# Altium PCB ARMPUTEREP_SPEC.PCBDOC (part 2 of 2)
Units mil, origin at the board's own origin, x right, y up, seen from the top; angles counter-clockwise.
Board outline 6000 x 4000 mil, 2 copper layers (Top Layer, Bottom Layer); 67 components, 140 nets, 541 pads, 398 vias.
Unrouted connection lines stored in the file: 6.
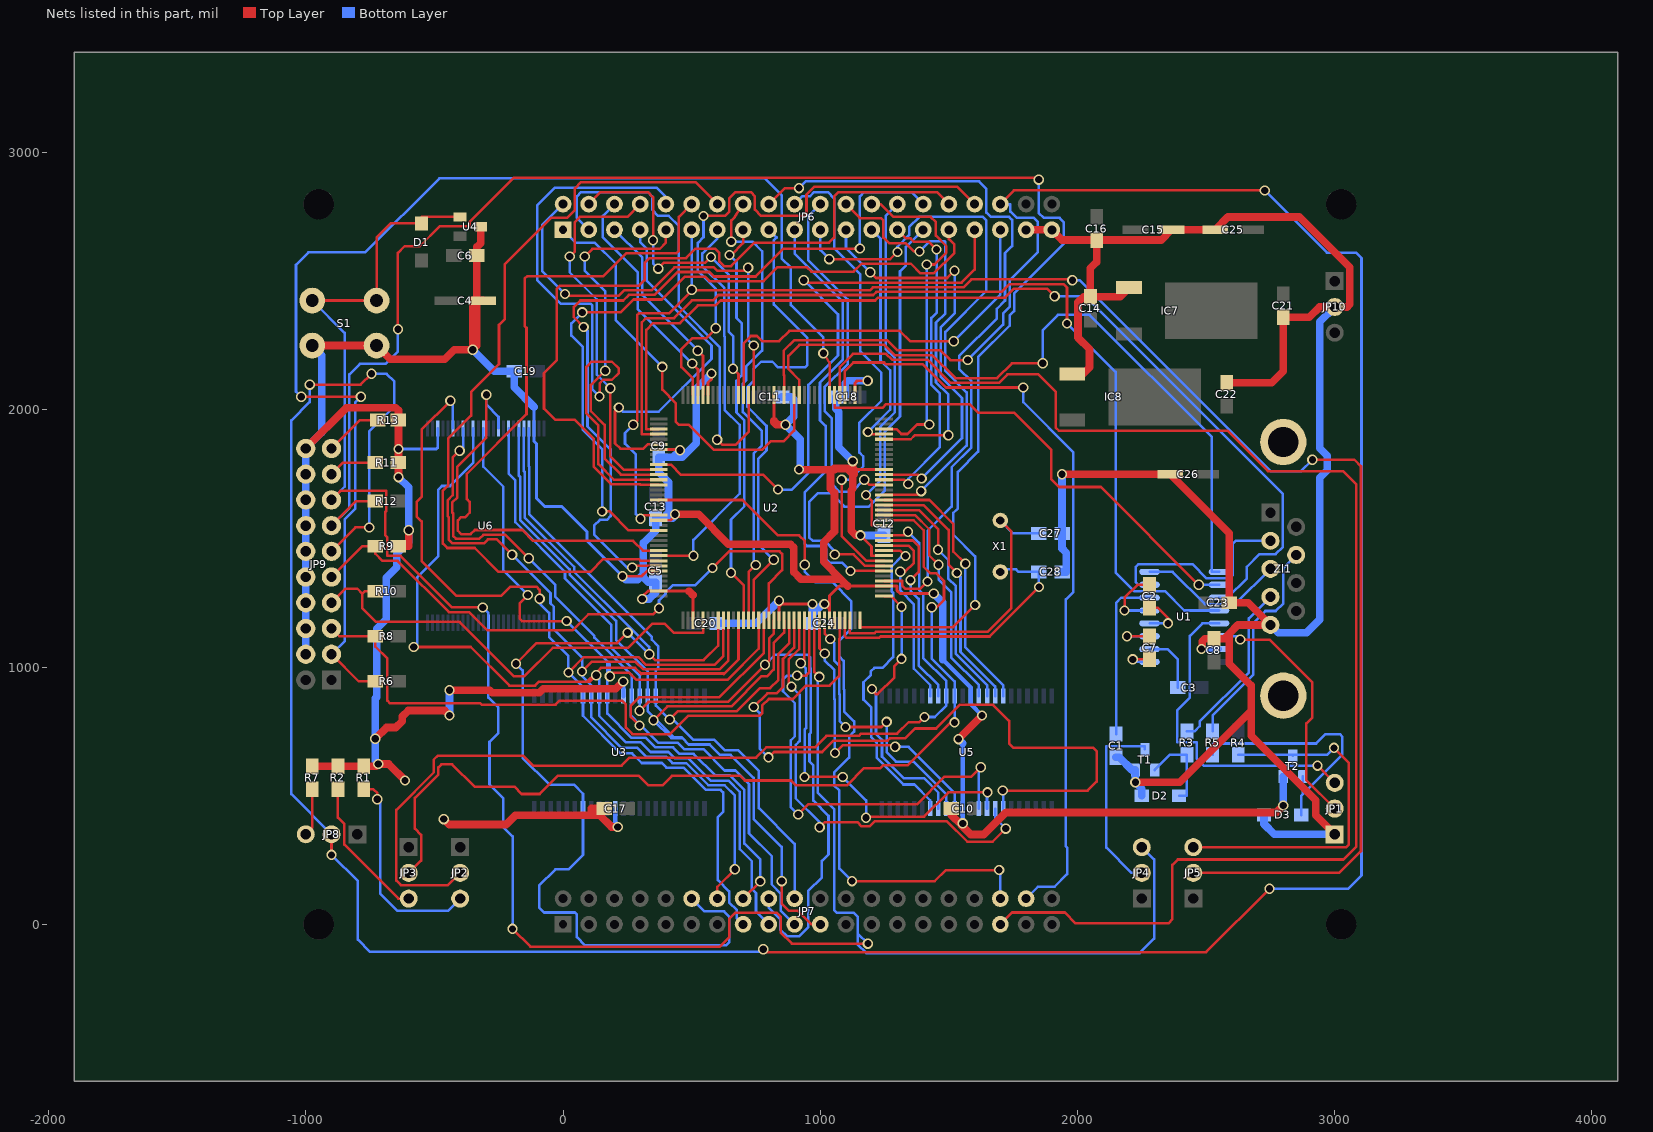
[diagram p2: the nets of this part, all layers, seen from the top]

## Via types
v1: diameter 40, hole 28, Top Layer to Bottom Layer, 398 vias

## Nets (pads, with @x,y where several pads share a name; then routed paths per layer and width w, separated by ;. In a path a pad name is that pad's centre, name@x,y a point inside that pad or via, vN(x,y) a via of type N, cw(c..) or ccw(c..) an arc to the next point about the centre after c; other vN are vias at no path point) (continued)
D7: JP7.12 U2.116 U3.16 U6.44 | length 4426.2
  Top Layer w10: v1(-183,1013) -103,1093 210,1093 v1(251,1134) ; v1(335,1050) 358,1027 546.53,1027 603.31,1083.78 U2.116@603.31,1182.01
  Bottom Layer w10: v1(-183,1013) -157,987 -157,647 -53,543 42.14,543 77.56,507.58 U3.16@77.56,450 77.56,270 21.56,214 -30,214 -93,151 -93,65 -74,46 46,46 54,38 54,-50 86,-82 634,-82 646,-70 646,30 626,50 550,50 JP7.12@500,100 ; U6.44@-152.36,1927.95 -152.36,1762 -149,1758.64 -149,1582.41 43.52,1389.89 43.52,1370 265.26,1148.26 335,1078.52 v1(335,1050) v1(251,1134)
D8: JP7.15 U2.117 U3.29 U6.30 | length 3912.3
  Top Layer w10: v1(-438,2035) -550,1923 -550,1661.5 -569.5,1642 -569.5,1585.5 -550,1566 -550,1411.97 -414.79,1276.76 -241,1276.76 -204.76,1313 -104,1313 -91,1300 v1(-91,1266) ; v1(21,979) 80.5,1038.5 292.5,1038.5 322,1009 587.99,1009 622.99,1044 U2.117@622.99,1182.01
  Bottom Layer w10: v1(-438,2035) -427.95,2024.95 U6.30@-427.95,1927.95 ; v1(-91,1266) -91,1247.57 -54,1210.57 -54,1117.67 21,1042.67 v1(21,979) 77.56,922.44 U3.29@77.56,887.01 77.56,810.77 224.01,664.31 268.69,664.31 306,627 384,627 402.01,608.99 469.01,608.99 555.3,522.7 612.3,522.7 622,513 622,437 602,417 602,172 646,128 646,85 676,55 676,24 JP7.15@700,0
D9: JP7.14 U2.118 U3.30 U6.32 | length 3382.5
  Top Layer w10: v1(-402,1841) -429,1814 -429,1668 -449,1648 -449,1587 -445,1583 -445,1496 -430,1481 -307,1481 -291.81,1496.19 -257.19,1496.19 v1(-198,1437) ; v1(74,983) 111.5,1020.5 282.5,1020.5 312,991 607.53,991 642.68,1026.15 U2.118@642.68,1182.01 ; JP7.14@600,100 600,146 v1(668,214)
  Bottom Layer w10: v1(-402,1841) -388.58,1854.42 U6.32@-388.58,1927.95 ; v1(-198,1437) -48.72,1287.72 -48.72,1247.29 -36,1234.57 -36,1146.98 74,1036.98 v1(74,983) 74,965.06 109.06,930 U3.30@109.06,887.01 109.06,805.15 228.09,686.12 288.65,686.12 322.77,652 400.32,652 425.33,626.99 479.01,626.99 565.3,540.7 628.1,540.7 668,500.8 v1(668,214)
D10: JP7.17 U2.120 U3.31 U6.34 | length 3940.4
  Top Layer w10: v1(-580,1078) -358.76,1078 -208.81,928.05 -109.12,928.05 -93.62,943.55 94,943.55 ; v1(129,968) 104.55,943.55 94,943.55 ; 304.54,973 280.54,997 147.45,997 123.72,973.28 94,943.55 ; 304.54,975 625,975 ; 625,973 682.05,1030.05 U2.120@682.05,1182.01
  Bottom Layer w10: v1(-580,1078) -566,1092 -566,1350 -485,1431 -485,1690 -471,1704 -438.98,1704 -349.21,1793.77 U6.34@-349.21,1927.95 ; v1(129,968) 140.55,956.45 U3.31@140.55,887.01 140.55,810.81 243.31,708.06 301.82,708.06 339.87,670 409.61,670 434.62,644.99 487.7,644.99 574,558.7 643.21,558.7 687,514.9 687,292.22 734,245.22 734,137 750,121 750,50 JP7.17@800,0
D11: JP7.16 U2.124 U3.32 U6.36 | length 3386.1
  Top Layer w10: v1(-137,1280) -169,1248 -169,1188 -160,1179 v1(14,1179) ; v1(182,964) 195.54,977.54 257.46,977.54 284.75,950.25 639.25,950.25 760.79,1071.79 U2.124@760.79,1182.01 ; JP7.16@700,100 v1(767,167)
  Bottom Layer w10: U6.36@-309.84,1927.95 -309.84,1778.84 -232,1701 -232,1375 v1(-137,1280) ; v1(14,1179) 172.05,1020.95 ; v1(182,964) 182,1011 172.05,1020.95 ; v1(767,167) 767,251.93 705,313.93 705,522.54 648.54,579 592,579 508.01,662.99 452.62,662.99 427.61,688 359,688 320.94,726.06 264.94,726.06 172.05,818.95 U3.32@172.05,887.01 172.05,964 172.05,1020.95
D12: JP7.19 U2.125 U3.35 U6.39 | length 3890
  Top Layer w10: v1(-298,2059) -298,1892.3 -411,1779.3 -411,1660 -431,1640 -431,1601 -427,1597 -427,1510 -416,1499 -325,1499 -309.81,1514.19 -224.19,1514.19 v1(-133,1423) ; v1(297,773) 264,806 264,850 297,883 608,883 780.47,1055.47 U2.125@780.47,1182.01
  Bottom Layer w10: v1(-298,2059) -298,2020.21 -250.79,1973 U6.39@-250.79,1927.95 ; v1(-133,1423) -30.72,1320.72 -30.72,1274.37 122,1121.64 122,1115 267,970 267,908 266.54,908 U3.35@266.54,887.01 266.54,855.85 264,853.32 264,811.61 299.81,775.81 v1@302.61,773 ; v1(297,773) v1@302.61,773 ; JP7.19@900,0 846,54 846,120.39 811.39,155 811.39,264.98 723,353.37 723,545.55 670.44,598.11 628.25,598.11 545.37,680.99 470.62,680.99 445.61,706 369.61,706 v1@302.61,773
D13: JP7.18 U2.127 U3.36 U6.41 | length 3643.1
  Top Layer w10: v1(297,830) 332,865 641,865 v1(785,1009) 801,1025 801,1111.16 819.84,1130 U2.127@819.84,1182.01
  Bottom Layer w10: U6.41@-211.42,1927.95 -211.42,1752.42 -185,1726 -185,1563 7.52,1370.48 7.52,1344.49 188,1164.02 188,1075 298.55,964.45 U3.36@298.55,887.5 298.55,831.55 v1(297,830) ; v1(785,1009) 824,1048 950,1048 960.84,1037.16 960.84,996.84 963,994.68 963,745 958,740 958,632.94 973,617.94 973,480.64 1032,421.64 1032,272.33 1006,246.33 1006,182 952.67,128.67 952.67,-11.68 918.35,-46 870,-46 845.5,-21.5 845.5,18.85 800,64.35 JP7.18@800,100
D14: JP7.21 U2.129 U3.37 U6.43 | length 3440.4
  Top Layer w10: v1(352,793) 406,847 654,847 772,965 794,965 819,990 819,1093.81 859.21,1134.02 U2.129@859.21,1182.01 ; v1(850,168) 850,81.5 879,52.5 913.5,52.5 966,0 JP7.21@1000,0
  Bottom Layer w10: U6.43@-172.05,1927.95 -172.05,1744 -167,1738.95 -167,1572.5 25.52,1379.98 25.52,1360.2 206.14,1179.58 206.14,1105.86 329.53,982.47 U3.37@329.53,887.01 329.53,866 330,866 330,827.99 358.5,799.5 430.95,727.04 460.57,727.04 463.61,724 ; v1(352,793) 421,724 463.61,724 ; v1(850,168) 850,301 741,410 741,569.11 651.11,659 610,659 570.01,698.99 488.62,698.99 463.61,724
D15: JP7.20 U2.130 U3.38 U6.45 | length 3084.1
  Top Layer w10: v1(414.75,796.25) 447.5,829 676,829 765,918 805,918 837,950 837,1050.23 878.9,1092.13 U2.130@878.9,1182.01
  Bottom Layer w10: U6.45@-132.68,1927.95 -132.68,1780 -131,1778.32 -131,1594 345.5,1117.5 345.5,1106.31 370,1081.81 370,997 361.02,988.02 U3.38@361.02,887.01 361.02,849.98 v1(414.75,796.25) 427.36,796.25 506.62,716.99 588.01,716.99 628,677 680.22,677 761,596.22 761,451.92 900,312.92 JP7.20@900,100
D16: U2.131 U5.7 | length 2697.3
  Top Layer w10: v1(741,845) 794,898 830,898 855,923 855,1032.23 898.58,1075.81 U2.131@898.58,1182.01 ; v1(799,649) 820,670 1007,670 1051,714 1262,714 1271,723 1330.26,723 1368.65,761.39 1450.39,761.39 1542,853 1672,853 1734.27,790.73 1734.27,702.73 1750,687 2060,687 2074,673 2074,555 2039,520 v1(1709,520)
  Bottom Layer w10: v1(741,845) 764.49,821.51 764.49,683.51 v1(799,649) ; v1(1709,520) 1711.02,517.98 U5.7@1711.02,450
D17: U2.132 U5.8 | length 1780.5
  Top Layer w10: v1(888,924) 877,935 877,1028.77 918.27,1070.04 U2.132@918.27,1182.01 ; v1(997.42,377) 1017.42,397 1144,397 1160,381 1192,381 1212,401 1491.54,401 1571.54,321 1670,321 v1(1721,372)
  Bottom Layer w10: v1(888,924) 919.54,892.46 919.54,712.41 904.67,697.53 904.67,489.75 997.42,397 v1(997.42,377) ; U5.8@1679.53,450 1679.53,413.47 v1(1721,372)
D18: U2.133 U5.9 | length 1547.5
  Top Layer w10: v1(924,1015) 937.95,1028.95 U2.133@937.95,1182.01 ; v1(939,573) v1(1087,573) ; v1(1178,414) 1183,419 1404,419 1498,513 v1(1650,513)
  Bottom Layer w10: v1(924,1015) 942.84,996.16 942.84,978.84 945,976.68 945,763 939,757 v1(939,573) ; v1(1087,573) 1178,482 v1(1178,414) ; U5.9@1648.03,450 1648.03,511.03 v1(1650,513)
D19: U2.134 U5.10 | length 1828.9
  Top Layer w10: v1(910,967) 944.64,967 957.64,980 U2.134@957.64,1182.01 ; v1(914,427) 953,466 1375.23,466 1483.23,574 1587,574 v1(1624,611)
  Bottom Layer w10: v1(910,967) 870,967 855,952 855,906 901.54,859.46 901.54,731.08 886,715.53 886,455 v1(914,427) ; U5.10@1616.54,450 1616.54,603.54 v1(1624,611)
D20: U2.136 U5.13 | length 1155.9
  Top Layer w10: U2.136@997.01,1182.01 997.01,1072.99 v1(1017,1053) ; v1(1057,666) 1087,696 1285,696 v1(1291,690)
  Bottom Layer w10: v1(1017,1053) 1017,1026.5 1055,988.5 1055,876 1057,874 v1(1057,666) ; v1(1291,690) 1343,690 1522.05,510.95 U5.13@1522.05,450
D21: U2.137 U5.14 | length 1090.7
  Top Layer w10: U2.137@1016.69,1182.01 1016.69,1131.31 v1(1039,1109) ; v1(1098,767) 1238,767 v1(1258,787)
  Bottom Layer w10: v1(1039,1109) 1055,1093 1055,1024.5 1073,1006.5 1073,896 1075,894 1075,790 v1(1098,767) ; v1(1258,787) 1258,669 1294.23,632.77 1363.23,632.77 1490.55,505.45 U5.14@1490.55,450
D22: U2.1 U5.15 | length 1114
  Top Layer w10: v1(1201,915) 1201,910 1216,895 1223,895 1288,960 1288,1004 v1(1316,1032) ; U2.1@1247.99,1275.51 1275,1275.51 v1(1316,1234.51)
  Bottom Layer w10: v1(1201,915) 1216.72,899.28 1216.72,740 1240,716.72 1240,652.23 1324.23,568 1402.54,568 1459.06,511.49 U5.15@1459.06,450 ; v1(1316,1032) v1(1316,1234.51)
D23: U2.10 U5.16 | length 1303.5
  Top Layer w10: U2.10@1247.99,1452.68 1310.32,1452.68 v1(1331,1432)
  Bottom Layer w10: v1(1331,1432) 1318,1432 1278,1392 1278,1293 1283,1288 1283,1038.54 1241.46,997 1210,997 1197,984 1197,970 1168,941 1168,873.23 1198.72,842.5 1198.72,726.51 1220,705.23 1220,646.77 1323.26,543.51 1365.49,543.51 1427.56,481.44 U5.16@1427.56,450
D24: U2.11 U5.29 | length 770.9
  Top Layer w10: U2.11@1247.99,1472.36 1343.82,1472.36 1364,1452.18 1364,1405 1330,1371 v1(1311,1371)
  Bottom Layer w10: v1(1311,1371) 1311,1297 1364,1244 1364,993.56 1427.56,930 U5.29@1427.56,887.01
D25: U2.12 U5.30 | length 783.8
  Top Layer w10: U2.12@1247.99,1492.05 1360.14,1492.05 1382,1470.18 1382,1369 v1(1351,1338)
  Bottom Layer w10: v1(1351,1338) 1351,1296 1382,1265 1382,1007 1459.06,929.94 U5.30@1459.06,887.01
D26: JP2.2 U2.13 U5.31 | length 3754
  Top Layer w10: JP2.2@-400,200 -448,152 -630,152 -648,170 -648,445 -502.62,590.38 -502.62,640 -486.62,656 -155,656 -116,617 228,617 259,648 750,648 790,688 978.94,688 1023.89,732.95 1151,732.95 1159.05,741 1299,741 1344,786 1385,786 v1(1405,806) ; U2.13@1247.99,1511.73 1326.73,1511.73 v1(1341,1526)
  Bottom Layer w10: v1(1341,1526) 1384,1483 1384,1300 1400,1284 1400,1036 1490.55,945.45 U5.31@1490.55,887.01 1490.55,851.55 1445,806 v1(1405,806)
D27: JP3.2 U2.16 U5.32 | length 3746.2
  Top Layer w10: JP3.2@-600,200 -552,248 -552,348 -576,372 -576,491 -484.62,582.38 -484.62,610 -472.62,622 -431,622 -343.98,534.98 -188.98,534.98 -160.72,506.72 -90.64,506.72 -19.36,578 294,578 332,540 385.79,540 422.79,577 689,577 707,559 887,559 906,540 1103,540 1170,607 1233.79,607 1245.79,619 1340.61,619 1506.66,785.05 v1(1522.05,785.05) ; U2.16@1247.99,1570.79 1363.23,1570.79 1402,1532.02 1402,1390 1427,1365 1450,1365 1481,1334 1481,1261 1453,1233 v1(1433,1233)
  Bottom Layer w10: v1(1433,1233) 1433,1033.02 1522.05,943.97 U5.32@1522.05,887.01 v1(1522.05,785.05)
D28: U2.17 U5.35 | length 927
  Top Layer w10: U2.17@1247.99,1590.47 1369,1590.47 1423.65,1535.83 1423.65,1434.35 v1(1460,1398)
  Bottom Layer w10: v1(1460,1398) 1460,1340.05 1509,1291.05 1509,1037.6 1616.54,930.06 U5.35@1616.54,887.01
D29: U2.18 U5.36 | length 968.2
  Top Layer w10: U2.18@1247.99,1610.16 1383.84,1610.16 1457.89,1536.11 v1(1457.89,1456.11)
  Bottom Layer w10: v1(1457.89,1456.11) 1496.67,1417.33 1496.67,1345 1527,1314.67 1527,1051.55 1648.55,930 U5.36@1648.55,887.5
D30: U2.19 U5.37 | length 1011.9
  Top Layer w10: U2.19@1247.99,1629.84 1402.16,1629.84 1499,1533 1499,1398 v1(1531,1366)
  Bottom Layer w10: v1(1531,1366) 1545,1352 1545,1059.01 1679.53,924.48 U5.37@1679.53,887.01
D31: U2.20 U5.38 | length 1057.7
  Top Layer w10: U2.20@1247.99,1649.53 1424.47,1649.53 1517,1557 1517,1449 v1(1564,1402)
  Bottom Layer w10: v1(1564,1402) 1564,1077.02 1711.02,930 U5.38@1711.02,887.01
GND: C1.1 C4.2 C5.2 C6.2 C8.2 C9.2 C10.2 C11.1 C12.1 C13.2 C14.2 C15.2 C16.2 C17.2 C18.2 C19.2 C20.2 C21.2 C22.2 C23.2 C24.2 C25.2 C26.2 C27.2 C28.2 D2.1 D3.1 IC7.1 IC8.1 JP1.1 JP6.37 JP6.39 JP9.4 JP9.6 JP9.8 JP9.10 JP9.12 JP9.14 JP9.16 JP9.18 JP9.20 JP10.2 R1.2 R2.2 R7.2 R9.2 R11.2 R13.2 S1.2 T1.2 T2.2 U1.15 U2.3 U2.9 U2.26 U2.38 U2.54 U2.67 U2.79 U2.93 U2.103 U2.107 U2.111 U2.128 U2.138 U2.139 U3.12 U3.34 U4.3 U5.12 U5.34 U6.27 U6.46 Zl1. Zl1.5 | length 26317.6
  Top Layer w11.22: v1(230.82,1353.18) 305.06,1353.18 325.82,1373.94 U2.103@372.01,1373.94 ; v1(308,1265) 308,1273.2 330,1295.2 U2.107@372.01,1295.2 490,1295.2 ; U2.93@372.01,1570.79 417.79,1570.79 v1@435,1588 ; U2.79@372.01,1846.38 v1@451.62,1846.38 ; U2.111@504.88,1182.01 504.88,1280.32 ; U2.67@563.94,2057.99 563.94,2106.05 577,2119.12 v1(577,2141) ; 819.84,1952 819.84,1957.16 U2.54@819.84,2057.99 ; U2.128@839.53,1182.01 839.53,1234.53 ; v1(839.53,1258) 839.53,1234.53 ; v1(970,1245) 850,1245 839.53,1234.53 ; v1(1016,1245) 1036.38,1224.62 ; U2.139@1056.06,1211 U2.139@1056.06,1182.01 U2.138@1036.38,1182.01 1036.38,1224.62 ; 1132.35,1767.64 U2.26@1247.99,1767.64 ; U2.38@1134.8,2057.99 1134.8,2103.8 1144,2113 v1(1184,2113) ; v1(1156,1512) 1199,1469 1199,1432.99 U2.9@1247.99,1432.99 ; v1(1441,1286) 1310,1286 1299,1297 1299,1314.88 U2.3@1247.99,1314.88 1107.12,1314.88 1074,1314.88 1036.38,1277.26 1036.38,1245 1036.38,1224.62
  Top Layer w30: JP9.20@-1000,1850 -842,2008 -650,2008 -640,1998 R13.2@-640,1960 v1(-640,1848) R11.2@-640,1795 v1(-640,1738.5) ; R7.2@-975,615 R2.2@-875,615 R1.2@-775,615 -726,615 v1(-718,623) -678,623 v1(-614,559) ; S1.2@-975,2250 S1.2@-725,2250 -671.71,2196.71 -460.4,2196.71 -423.1,2234 v1(-351,2234) ; v1(-729.65,721.35) -686,765 -650,765 -625,790 -625,808 -602,831 -460,831 v1(-441,812) ; R9.2@-640,1470 -600,1470 v1(-600,1531.78) ; v1(-464,409) -442.75,387.75 -221.69,387.75 -185,424.44 110.56,424.44 ; v1(-441,910) -285.07,910 -275.12,900.05 -92.7,900.05 -77.48,915.28 205.28,915.28 v1(234,944) ; U4.3@-320,2712 -320,2647.87 -335,2632.87 C6.2@-335,2600 C4.2@-335,2425 ; C4.2@-310,2425 C4.2@-335,2425 ; C17.2@160,450 110.56,450 110.56,424.44 ; v1(212.74,378.26) 188.74,378.26 142.56,424.44 110.56,424.44 ; v1(435,1594) 527,1594 643,1478 884,1478 897,1465 897,1370 925,1342 1080,1342 ; v1@451.62,1846.38 v1(455,1843) ; 490,1295.2 504.88,1280.32 ; 819.84,1952 829.84,1942 835,1942 ; 819.84,1957.16 835,1942 ; v1(865,1942) 835,1942 ; v1(917.36,1768.36) 917.36,1767.64 1050,1767.64 ; 1107.12,1314.88 1080,1342 ; v1(1126,1800.64) 1126,1750 ; 1132.35,1767.64 1132.35,1749.99 1126,1743.64 ; v1(1156,1512) 1138,1512 1120,1530 1120,1688 1126,1694 1126,1743.64 ; C10.2@1510,450 1510,424 1547.54,386.46 v1@1553.54,380.46 ; v1(1537,720) v1(1629.03,812.03) ; v1(1553.54,392.46) v1@1553.54,380.46 ; JP6.37@1800,2700 JP6.39@1900,2700 1940,2660 C16.2@2075,2660 ; v1(1940,1750) C26.2@2360,1750 2590,1520 C23.2@2590,1250 2664,1250 Zl1.5@2750,1164 2624,1164 2590,1130 ; IC8.1@1980,2140 2021.58,2140 2047,2165.42 2047,2236 2002,2281 2002,2418 2024,2440 C14.2@2050,2440 ; IC7.1@2200,2475 2165,2440 C14.2@2050,2440 ; v1(2225,552) 2397,552 2675,830 ; v1(2482,1070) 2485,1073 2485,1100 2495,1110 C8.2@2530,1110 2570,1110 2590,1130 ; C22.2@2580,2105 2755,2105 2800,2150 C21.2@2800,2360 2901,2360 2941,2400 JP10.2@3000,2400 3048,2400 3058,2410 3058,2554 2862,2750 2585,2750 C25.2@2535,2700 C15.2@2365,2700 2325,2660 C16.2@2075,2660 ; v1(2800,462) 2773,435 1722,435 1636,349 1585,349 v1@1553.54,380.46 ; JP1.1@3000,350 2926,424 2926,482 2675,733 2675,830 ; v1(-351,2234) -335,2250 C4.2@-335,2425 ; v1(-351,2234) -351,2425 C4.2@-335,2425 ; 1050,1767.64 1056.78,1767.64 1060.88,1771.74 ; 1050,1767.64 1040,1757.64 1040,1693 1055,1678 1055,1527 1013,1485 1013,1409 1080,1342 ; 1050,1767.64 1054.11,1771.74 1060.88,1771.74 ; 1060.88,1771.74 1104.26,1771.74 1126,1750 ; 1126,1743.64 1126,1750 ; C14.2@2050,2440 2050,2550 2075,2575 C16.2@2075,2660 ; 2590,1130 2590,1013 2675,928 2675,830
  Bottom Layer w11.22: v1(-640,1848) -492.01,1848 -487.01,1853 U6.27@-487.01,1927.95 ; -112.99,2010.99 U6.46@-112.99,1927.95 -112.99,1878 -103,1868.01 -103,1656 -71,1624 -5,1624 93,1526 93,1491 v1(230.82,1353.18) 245,1339
  Bottom Layer w16.83: v1@203.54,387.46 U3.12@203.54,450 ; v1(234,944) 235.04,942.96 U3.34@235.04,887.01 ; 1476,1029.62 1585.04,920.58 U5.34@1585.04,887.01 1585.04,856.02 v1(1629.03,812.03) ; v1(1553.54,392.46) U5.12@1553.54,450 1553.54,703.46
  Bottom Layer w22.8: v1(2482,1070) U1.15@2550,1070
  Bottom Layer w30: JP9.4@-1000,1050 JP9.6@-1000,1150 JP9.8@-1000,1250 JP9.10@-1000,1350 JP9.12@-1000,1450 JP9.14@-1000,1550 JP9.16@-1000,1650 JP9.18@-1000,1750 JP9.20@-1000,1850 -937.71,1912.29 -937.71,2212.71 S1.2@-975,2250 ; v1(-718,623) -729.65,634.65 v1(-729.65,721.35) -729.65,878.28 -724,883.93 -724,1149 -687,1186 -687,1347 -646,1388 -646,1440 -600,1486 v1(-600,1531.78) -600,1698.5 v1(-640,1738.5) ; v1(-441,812) v1(-441,910) ; v1(-351,2234) -267,2150 C19.2@-190,2150 -190,2088 -112.99,2010.99 ; v1@203.54,387.46 v1(212.74,378.26) ; 245,1339 290,1339 312,1361 ; v1(308,1265) 335,1265 360,1290 C5.2@360,1330 332,1330 312,1350 312,1361 ; v1@435,1588 426.21,1579.21 420.21,1579.21 ; v1(435,1594) 432,1591 420.21,1579.21 ; v1(455,1843) 427.43,1815.43 ; v1(577,2141) 518,2082 518,1870 473,1825 463.43,1815.43 455,1815.43 427.43,1815.43 ; C20.2@600,1170 751.53,1170 v1(839.53,1258) ; C11.1@850,2050 887,2050 897,2040 897,1974 v1(865,1942) 922,1885 922,1773 v1(917.36,1768.36) ; C24.2@970,1170 970,1205 ; v1(970,1245) 970,1205 ; v1(1016,1245) 1010,1245 990,1225 970,1205 ; v1(1126,1800.64) 1072,1854.64 1072,1992 1060,2004 C18.2@1060,2050 1097,2050 1097,2103.12 1106.88,2113 v1(1184,2113) ; v1(1156,1512) 1156.27,1511.73 C12.1@1247.99,1511.73 ; v1(1441,1286) 1476,1251 1476,1029.62 ; v1(1537,720) 1553.54,703.46 ; C28.2@1940,1370 1956,1370 1956,1445 1940,1461 C27.2@1940,1520 v1(1940,1750) ; C1.1@2150,650 2162,650 2212,600 T1.2@2225,600 v1(2225,552) 2250,527 D2.1@2250,500 ; D3.1@2725,425 2725,390 2765,350 JP1.1@3000,350 ; Zl1.5@2750,1164 2781,1133 2890,1133 2942,1185 2942,1736 2971,1765 2971,1822 2942,1851 2942,2342 JP10.2@3000,2400 ; v1(2800,462) T2.2@2800,575 ; 312,1361 312,1482 360,1530 C13.2@360,1579.21 390,1579.21 ; 390,1579.21 420.21,1579.21 ; 390,1579.21 410,1599.21 410,1719.01 372.01,1757 C9.2@372.01,1815.43 427.43,1815.43
NetC1_2: C1.2 U1.6 | length 648.3
  Bottom Layer w10: C1.2@2150,740 2150,1250 2170,1270 U1.6@2280,1270
NetC2_1: C2.1 U1.5 | length 264.7
  Top Layer w10: v1(2183,1220) 2183,1270 2233,1320 C2.1@2280,1320
  Bottom Layer w10: v1(2183,1220) U1.5@2280,1220
NetC2_2: C2.2 U1.4 | length 180.6
  Top Layer w10: C2.2@2280,1230 2312,1230 2352,1190 v1(2352,1170)
  Bottom Layer w10: U1.4@2280,1170 v1(2352,1170)
NetC3_2: C3.2 U1.2 | length 236.6
  Bottom Layer w10: U1.2@2280,1070 2350,1070 2390,1030 C3.2@2390,920
NetC7_1: C7.1 U1.3 | length 176
  Top Layer w10: v1(2192,1120) C7.1@2280,1120
  Bottom Layer w10: v1(2192,1120) U1.3@2280,1120
NetC7_2: C7.2 U1.1 | length 134.1
  Top Layer w10: v1(2215,1030) C7.2@2280,1030
  Bottom Layer w10: v1(2215,1030) 2225,1020 U1.1@2280,1020
NetC27_1: C27.1 U2.142 X1.2 | length 1247.3
  Top Layer w10: U2.142@1115.12,1182.01 1115.12,1132 1211,1132 1216,1137 1650.54,1137 1743,1229.46 1743,1527 X1.2@1700,1570
  Bottom Layer w10: X1.2@1700,1570 1750,1520 C27.1@1850,1520
NetC28_1: C28.1 U2.141 X1.1 | length 1117.6
  Top Layer w10: U2.141@1095.43,1182.01 1095.43,1120 1101.43,1114 1229,1114 1234,1119 1658,1119 v1(1850,1311)
  Bottom Layer w10: X1.1@1700,1370 1709.54,1379.54 1761,1379.54 1770.54,1370 C28.1@1850,1370 v1(1850,1311)
NetD2_2: D2.2 R3.2 T1.1 | length 339.9
  Bottom Layer w10: T1.1@2300,600 2360,660 R3.2@2425,660 2425,500 D2.2@2395,500
NetD3_2: D3.2 R5.2 T2.1 | length 1007.3
  Bottom Layer w10: R5.2@2525,660 2525,703 2928,703 2964,739 3020,739 3030,729 3030,660 2875,505 ; D3.2@2870,425 2870,500 2875,505 ; T2.1@2875,575 2875,505
NetJP1_2: JP1.2 U1.14 | length 982.6
  Top Layer w10: v1(2633,1107) 2746,1107 2913,940 2913,804 2890,781 2890,560 JP1.2@3000,450
  Bottom Layer w10: U1.14@2550,1120 2620,1120 v1(2633,1107)
NetJP1_3: JP1.3 U1.13 | length 1282.9
  Top Layer w10: v1(2933,617) JP1.3@3000,550
  Bottom Layer w10: U1.13@2550,1170 2486,1170 2437,1121 2437,882 2387,832 2387,707 2463,707 2463,644 2490,617 v1(2933,617)
NetJP2_3: JP2.3 R1.1 | length 812.8
  Top Layer w10: R1.1@-775,525 -737,525 -722,510 v1(-722,486)
  Bottom Layer w10: v1(-722,486) -711,475 -711,120 -643,52 -448,52 JP2.3@-400,100
NetJP3_3: JP3.3 R2.1 | length 562.3
  Top Layer w10: R2.1@-875,525 -875,415 -850,390 -850,310 -640,100 JP3.3@-600,100
NetJP4_2: JP4.2 T1.3 | length 736.6
  Bottom Layer w10: JP4.2@2250,200 2210,200 2112,298 2112,693 2262,693 T1.3@2262,680
NetJP5_3: JP5.3 R4.2 T2.3 | length 1396.9
  Top Layer w10: JP5.3@2450,300 3045,300 3055,310 3055,628 v1(2997,686)
  Bottom Layer w10: R4.2@2625,660 T2.3@2837,660 ; T2.3@2837,655 T2.3@2837,660 ; v1(2997,686) 2971,660 T2.3@2837,660
NetJP8_3: JP8.3 R7.1 | length 185.4
  Top Layer w10: JP8.3@-1000,350 -975,375 R7.1@-975,525
NetJP9_17: JP9.17 R11.1 | length 188.6
  Top Layer w10: JP9.17@-900,1750 -855,1795 R11.1@-730,1795
NetJP9_19: JP9.19 R13.1 | length 225.6
  Top Layer w10: JP9.19@-900,1850 -790,1960 R13.1@-720,1960
NetR3_1: R3.1 Zl1.4 | length 675.2
  Bottom Layer w10: R3.1@2425,750 2455,750 2475,770 2475,788 2666,979 2666,1189 Zl1.4@2750,1273
NetR5_1: R5.1 Zl1.7 | length 844.1
  Bottom Layer w10: R5.1@2525,750 2525,812 2684,971 2684,1172 2730,1218 2770,1218 2800,1248 2800,1386 Zl1.7@2850,1436
NetU1_7: U1.7 Zl1.2 | length 799
  Bottom Layer w10: U1.7@2280,1320 2236,1320 2227,1329 2227,1390 2237,1400 2446.46,1400 2501.46,1345 2590,1345 2603,1358 2603,1479 2615,1491 Zl1.2@2750,1491
NetU1_8: U1.8 Zl1.3 | length 578.5
  Bottom Layer w10: U1.8@2280,1370 2370,1370 2495,1245 2613,1245 Zl1.3@2750,1382
P0.0: U1.10 U2.42 | length 1906.2
  Top Layer w10: U2.42@1056.06,2057.99 1056.06,2009 1243,2009 1256,2022 1581,2022 1613.88,1989.12 1753.38,1989.12 1898,1844.5 1898,1730 1928,1700 2091,1700 v1(2471,1320)
  Bottom Layer w10: v1(2471,1320) U1.10@2550,1320
P0.1: U1.9 U2.49 | length 2813.4
  Top Layer w10: U2.49@918.27,2057.99 918.27,2116.73 876,2159 876,2210 919,2253 1249,2253 1289,2213 1435,2213 1525,2123 1687.24,2123 1745.24,2181 v1(1865,2181)
  Bottom Layer w10: v1(1865,2181) 1865,2310 1924,2369 2047,2369 2522,1894 2522,1370 U1.9@2550,1370
P0.2: JP6.1 U2.50 | length 1644.7
  Top Layer w10: v1(386,2167) 386,2078.46 438,2026.46 438,1954 450,1942 488.98,1942 585.34,1845.64 774.64,1845.64 806.73,1877.73 856.73,1877.73 898.58,1919.58 U2.50@898.58,2057.99
  Bottom Layer w10: JP6.1@0,2700 51,2649 124,2649 205,2568 205,2348 v1(386,2167)
P0.3: JP6.2 U2.58 | length 1698.1
  Top Layer w10: v1(8,2450) 8,2443 216,2443 237.86,2464.86 343.86,2464.86 433,2554 586.5,2554 600,2540.5 707.5,2540.5 v1(719.5,2552.5) ; v1(741,2250.5) 741,2087.1 741.1,2087 U2.58@741.1,2057.99
  Bottom Layer w10: JP6.2@0,2800 -80,2720 -80,2538 v1(8,2450) ; v1(719.5,2552.5) 719.5,2272 v1(741,2250.5)
P0.4: JP6.3 U2.59 | length 1833.7
  Top Layer w10: v1(599,1884) 619.36,1863.64 670.64,1863.64 721.42,1914.42 U2.59@721.42,2057.99
  Bottom Layer w10: JP6.3@100,2700 54,2746 54,2830 70,2846 330,2846 346,2830 346,2778 370,2754 411,2754 450,2715 450,2402.71 610,2242.71 610,1895 v1(599,1884)
P0.5: JP6.4 U2.61 | length 1366.6
  Top Layer w10: JP6.4@100,2800 146,2846 330,2846 350,2826 v1(350,2659) ; v1(370,2549) 393,2572 553,2572 v1(575,2594) ; v1(661,2160.05) 682.05,2139 U2.61@682.05,2057.99
  Bottom Layer w10: v1(350,2659) 350,2569 v1(370,2549) ; v1(575,2594) 645,2524 645,2302.85 661,2286.85 v1(661,2160.05)
P0.6: JP6.5 U2.68 | length 784.6
  Top Layer w10: v1(524,2230) 544,2210 544,2108.25 544.25,2108 U2.68@544.25,2057.99
  Bottom Layer w10: JP6.5@200,2700 308,2592 308,2446 v1(524,2230)
P0.7: JP6.6 U2.69 | length 914.1
  Top Layer w10: v1(502,2180) 524.57,2157.43 U2.69@524.57,2057.99
  Bottom Layer w10: JP6.6@200,2800 154.5,2754.5 154.5,2670.5 290,2535 290,2392 v1(502,2180)
P0.8: U1.11 U2.75 | length 3866.2
  Top Layer w10: U2.75@372.01,1925.12 324,1925.12 324,2311 350,2337 455,2337 524,2406 593.15,2406 612.15,2425 1213.59,2425 1224.59,2436 1719,2436 1754,2471 1882,2471 v1(1911,2442)
  Bottom Layer w10: v1(1911,2442) 2028.27,2442 2798,1672.27 2798,1467 2770,1439 2707,1439 2658,1390 2658,1345 2583,1270 U1.11@2550,1270
P0.9: U1.12 U2.76 | length 3870.3
  Top Layer w10: U2.76@372.01,1905.43 306,1905.43 306,2340 322.86,2356.86 431.64,2356.86 500.77,2426 583.5,2426 603.9,2446.4 1205.94,2446.4 1217.89,2458.36 1705.36,2458.36 1736,2489 1945,2489 1959,2475 v1(1959,2336)
  Bottom Layer w10: v1(1959,2336) 2147.96,2147.04 2147.96,1367.04 2220,1295 2340,1295 2415,1220 U1.12@2550,1220
P0.10: JP6.7 U2.78 | length 1399.5
  Top Layer w10: v1(217,2009) 202,1994 202,1870 223,1849 312,1849 329.06,1866.06 U2.78@372.01,1866.06
  Bottom Layer w10: v1(217,2009) 233,1993 372,1993 577.25,2198.25 577.25,2250 326,2501.25 326,2626 300,2652 JP6.7@300,2700
P0.11: JP6.8 U2.83 | length 1477
  Top Layer w10: v1(26,2596) 46,2616 46,2730 66,2750 250,2750 JP6.8@300,2800 ; v1(184,2084) 184,1819.01 235.38,1767.64 U2.83@372.01,1767.64
  Bottom Layer w10: v1(26,2596) 26,2534.98 131,2429.98 131,2137 v1(184,2084)
P0.12: JP6.9 U2.84 | length 1488.2
  Top Layer w10: v1(84,2596) 114,2626 376,2626 400,2650 JP6.9@400,2700 ; v1(164,2152) 108.49,2096.49 108.49,1994.51 162,1941 162,1810.36 224.41,1747.95 U2.84@372.01,1747.95
  Bottom Layer w10: v1(84,2596) 84,2541.5 164,2461.5 v1(164,2152)
P0.13: JP6.10 U2.85 | length 2446.2
  Top Layer w10: v1(142,2052) 142,2103 156,2117 190,2117 217,2144 217,2160 190,2187 110,2187 90.49,2167.49 90.49,1986.51 137,1940 137,1789 197.73,1728.27 U2.85@372.01,1728.27
  Bottom Layer w10: v1(142,2052) 113,2081 113,2407 108,2412 -8,2412 -101,2505 -101,2794 -31,2864 364,2864 400,2828 JP6.10@400,2800
P0.14: JP5.2 JP6.11 U2.92 | length 6540.2
  Top Layer w10: v1(273,1942) 288,1957 288,2368.42 294.44,2374.86 411.77,2374.86 501.41,2464.5 v1@502.5,2464.5 ; v1(301,1577) 314.47,1590.47 U2.92@372.01,1590.47 ; v1(500,2467) v1@502.5,2464.5 ; v1(1980,2504) 1977,2507 1587,2507 1556.5,2476.5 1204.87,2476.5 1192.87,2464.5 v1@502.5,2464.5 ; JP5.2@2450,200 3017.2,200 3102,284.8 3102,1780 3076,1806 v1(2913,1806)
  Bottom Layer w10: v1(273,1942) 241,1910 241,1868.6 283,1826.6 283,1595 v1(301,1577) ; v1(500,2467) JP6.11@500,2700 ; v1(1980,2504) 2008.4,2504 2750.4,1762 2869,1762 v1(2913,1806)
P0.15: JP6.12 U2.99 | length 2784.4
  Top Layer w10: U2.99@372.01,1452.68 310.32,1452.68 272,1491 -116,1491 -158,1533 -343,1533 -359,1517 -396,1517 -409,1530 -409,1570 -396,1583 -380,1583 -363,1600 -363,1642 -373.6,1652.6 -373.6,1751.58 -142,1983.18 -142,2319 -149,2326 -149,2510 -139,2520 157,2520 245,2608 440,2608 450,2618 450,2750 JP6.12@500,2800
P0.16: JP6.13 U2.100 | length 1560.6
  Top Layer w10: U2.100@372.01,1432.99 v1(507,1432.99)
  Bottom Layer w10: v1(507,1432.99) 507,1494 687,1674 687,1941 628,2000 628,2285 627,2286 627,2473 542,2558 542,2608 600,2666 JP6.13@600,2700
P0.17: JP6.14 U2.101 | length 3136.4
  Top Layer w10: U2.101@372.01,1413.31 301.69,1413.31 295,1420 156,1420 106,1370 -250.24,1370 -343.24,1463 -450,1463 -467,1480 -467,1686 -447,1706 -447,1888 -357,1978 -357,2070 -248.98,2178.02 -248.98,2330.02 -227,2352 -227,2565 -46,2746 15,2746 46,2777 46,2861 70,2885 515,2885 JP6.14@600,2800
P0.18: JP6.15 U2.121 | length 1626.2
  Top Layer w10: v1(647,2602) 654,2602 700,2648 JP6.15@700,2700 ; v1(653,1367) 701.73,1318.27 U2.121@701.73,1182.01
  Bottom Layer w10: v1(647,2602) 674.22,2574.78 674.22,2356.99 694,2337.21 694,2132.9 674.22,2113.11 674.22,1989.78 705,1959 705,1625.27 653,1573.27 v1(653,1367)
P0.19: JP6.16 U2.122 | length 1821
  Top Layer w10: v1(654,2654) 654,2736.5 667.68,2750.18 JP6.16@700,2800 ; U2.122@721.42,1182.01 721.42,1369.42 v1(749,1397)
  Bottom Layer w10: v1(654,2654) 736.5,2654 774,2616.5 774,2230 712,2168 712,2114.9 699,2101.9 699,1991.73 773,1917.73 773,1862 741,1830 741,1405 v1(749,1397)
P0.20: JP6.17 U2.123 | length 1917.1
  Top Layer w10: U2.123@741.1,1182.01 741.1,1339.1 v1(819,1417)
  Bottom Layer w10: JP6.17@800,2700 830,2670 819.5,2659.5 819.5,2409.5 950,2279 950,2175 940,2165 836,2165 814,2187 770,2187 741,2158 741,2112.87 717,2088.87 717,2012 791,1938 791,1842 759,1810 759,1477 v1(819,1417)
P0.21: JP6.18 U2.4 | length 2882.2
  Top Layer w10: JP6.18@800,2800 862,2862 v1(917,2862) ; U2.4@1247.99,1334.57 1318,1334.57 1318,1317 1330,1305 1389,1305 v1(1417,1333)
  Bottom Layer w10: v1(917,2862) 943,2888 1617,2888 1646,2859 1646,2767 1663,2750 1734.54,2750 1746,2738.54 1746,2637 1718,2609 1718,2424.36 1686.64,2393 1686.64,2355.72 1540,2209.07 1540,2159 1587,2112 1587,1853.35 1510.5,1776.85 1510.5,1623.5 1417,1530 v1(1417,1333)
P0.23: JP6.19 U2.6 | length 1752.4
  Top Layer w10: v1(1117.13,1373.94) U2.6@1247.99,1373.94
  Bottom Layer w10: JP6.19@900,2700 900,2608 1088,2420 1088,2195 999,2106 999,1959.19 1020.95,1937.24 1020.95,1759.76 939,1677.81 939,1480 948.16,1470.84 1009.16,1470.84 1023,1457 1023,1420 1038.02,1404.98 1086.09,1404.98 v1(1117.13,1373.94)
P0.24: JP6.20 U2.8 | length 1870.6
  Top Layer w10: v1(1083,1728) 1083,1510.31 1180,1413.31 U2.8@1247.99,1413.31
  Bottom Layer w10: JP6.20@900,2800 931,2831 961,2831 976,2846 1030,2846 1054,2822 1054,2629 1156,2527 1156,2226 1237,2145 1237,2035 1152,1950 1152,1834 1167,1819 1167,1780 1115,1728 v1(1083,1728)
P0.25: JP6.21 U2.21 | length 2218.9
  Top Layer w10: v1(1035,2586) 1272,2586 v1(1300,2614) ; U2.21@1247.99,1669.21 1377.21,1669.21 v1(1392,1684)
  Bottom Layer w10: JP6.21@1000,2700 1000,2621 v1(1035,2586) ; v1(1300,2614) 1300,2634 1345.5,2679.5 1345.5,2710 1385.5,2750 1632,2750 1646,2736 1646,2463 1486,2303 1486,2151.28 1569,2068.28 1569,1861 v1(1392,1684)
P0.27: JP6.22 U2.23 | length 1462
  Top Layer w10: v1(1170.58,1728.58) 1190.58,1708.58 U2.23@1247.99,1708.58
  Bottom Layer w10: JP6.22@1000,2800 954,2754 954,2581.43 1106,2429.43 1106,2177 1017,2088 1017,1994.68 1044,1967.68 1044,1712.98 1075.63,1681.35 1123.35,1681.35 v1(1170.58,1728.58)
P0.28: JP6.23 U2.25 | length 1635
  Top Layer w10: v1(1194,2535) 1216.5,2512.5 1493.5,2512.5 v1(1522,2541) ; U2.25@1247.99,1747.95 1379.05,1747.95 v1(1394,1733)
  Bottom Layer w10: JP6.23@1100,2700 1100,2629 v1(1194,2535) ; v1(1394,1733) 1551,1890 1551,2046 1468,2129 1468,2321 1522,2375 v1(1522,2541)
P0.29: JP6.24 U2.32 | length 1562.1
  Top Layer w10: JP6.24@1100,2800 1154.5,2745.5 1236.5,2745.5 1245.5,2736.5 1245.5,2670 1268.5,2647 1333,2647 1364,2616 v1(1386,2616) ; U2.32@1247.99,1885.75 1351.7,1885.75 1366.98,1901.03 v1(1498,1901.03)
  Bottom Layer w10: v1(1386,2616) 1426,2656 1483,2656 1486,2653 1486,2375 1450,2339 1450,2107.2 1498,2059.2 v1(1498,1901.03)
P0.30: JP6.25 U2.33 | length 918.4
  Top Layer w10: v1(1185,1914) 1193.57,1905.43 U2.33@1247.99,1905.43
  Bottom Layer w10: v1(1185,1914) 1272,2001 1272,2153.44 1234.16,2191.28 1234.16,2665.84 JP6.25@1200,2700
P1.16: JP6.26 U2.34 | length 1334.4
  Top Layer w10: JP6.26@1200,2800 1235,2800 1285,2750 1429,2750 1449,2730 1449,2677 1490,2636 1490,2611 1444,2565 v1(1414,2565) ; U2.34@1247.99,1925.12 1296,1925.12 1315.12,1906 1339,1906 1376,1943 v1(1424,1943)
  Bottom Layer w10: v1(1414,2565) 1414,1953 v1(1424,1943)
P1.17: JP6.27 U2.24 | length 1268.5
  Top Layer w10: U2.24@1247.99,1728.27 1325.73,1728.27 v1(1342,1712) ; JP6.27@1300,2700 1333,2667 1351,2667 1365,2653 1422,2653 v1(1452,2623)
  Bottom Layer w10: v1(1342,1712) 1342,1732 1465,1855 1465,2064.03 1432,2097.03 1432,2357 1452,2377 v1(1452,2623)
P1.18: JP6.28 U2.15 | length 1386.4
  Top Layer w10: v1(1178,1669) 1200,1647 1200,1551.1 U2.15@1247.99,1551.1
  Bottom Layer w10: v1(1178,1669) 1233,1724 1233,1933.69 1290,1990.69 1290,2201 1254,2237 1254,2754 JP6.28@1300,2800
P1.19: JP6.29 U2.7 | length 1912.7
  Top Layer w10: v1(1056,1438) 1129.31,1438 1173.69,1393.62 U2.7@1247.99,1393.62
  Bottom Layer w10: v1(1056,1438) 1056,1451.5 1016.23,1491.27 970,1491.27 957,1504.27 957,1642 990,1675 1043,1675 1094,1624 1189,1624 1251,1686 1251,1916 1310,1975 1310,2538 1333,2561 1333,2633 JP6.29@1400,2700
P1.20: JP6.30 U2.102 | length 2988.5
  Top Layer w10: v1(80,2322) 42,2360 42,2400 67,2425 234,2425 255.86,2446.86 355.86,2446.86 445,2536 569,2536 586.5,2518.5 748.35,2518.5 856.85,2627 v1(1154,2627) ; v1(269,1387) 275.62,1393.62 U2.102@372.01,1393.62
  Bottom Layer w10: v1(80,2322) 95,2307 95,1936 185,1846 185,1587 170,1572 143,1572 121,1550 121,1515 249,1387 v1(269,1387) ; v1(1154,2627) 1154,2830 1170,2846 1354,2846 JP6.30@1400,2800
P1.21: JP6.31 U2.95 | length 2792.5
  Top Layer w10: v1(75,2379) 224,2379 273.86,2428.86 384.79,2428.86 473.93,2518 551,2518 568.5,2500.5 779.75,2500.5 834.25,2555 947,2555 965,2537 1130,2537 1161,2568 1351.84,2568 1389.34,2530.5 1440.94,2530.5 1521,2610.56 1521,2643 1500,2664 JP6.31@1500,2700 ; v1(152,1605) 181.71,1605 255.3,1531.42 U2.95@372.01,1531.42
  Bottom Layer w10: v1(75,2379) 32,2336 32,2289 77,2244 77,1922.13 152,1847.13 v1(152,1605)
P1.22: JP6.32 U2.86 | length 3026.3
  Top Layer w10: U2.86@372.01,1708.58 301,1708.58 299.58,1710 188,1710 119,1779 119,1888 46,1961 -30,1961 -74,2005 -74,2143 -25,2192 -25,2470 -12,2483 295.21,2483 317,2504.79 317,2570 337,2590 478,2590 515,2627 591,2627 608,2610 608,2576 625.5,2558.5 653,2558.5 744.5,2650 1034,2650 1054,2670 1054,2830 1070,2846 1454,2846 JP6.32@1500,2800
P1.23: JP6.33 U2.82 | length 2344.6
  Top Layer w10: U2.82@372.01,1787.32 419.11,1787.32 459.43,1747 779,1747 v1(836,1690) ; v1(936,2504) 945.5,2494.5 1549,2494.5 1600,2545.5 JP6.33@1600,2700
  Bottom Layer w10: v1(836,1690) 889.21,1690 954,1754.79 954,2097 1069.01,2212.01 1069.01,2370.99 v1(936,2504)
P1.24: JP6.34 U2.70 | length 2150.3
  Top Layer w10: U2.70@504.88,2057.99 504.88,2121.57 460,2166.46 460,2236 502,2278 555,2278 v1(594,2317) ; v1(546,2754) 630,2754 646,2770 646,2822 670,2846 730,2846 746,2830 746,2778 770,2754 940,2754 946.34,2760.34 946.34,2836.34 978,2868 1532,2868 JP6.34@1600,2800
  Bottom Layer w10: v1(546,2754) 546,2671.27 524,2649.27 524,2540 594,2470 v1(594,2317)
P1.25: JP6.35 U2.60 | length 1579.1
  Top Layer w10: U2.60@701.73,2057.99 701.73,2258.73 730,2287 754,2287 774,2267 840,2267 880,2307 1309,2307 1349,2267 v1(1519,2267)
  Bottom Layer w10: v1(1519,2267) 1700,2448 JP6.35@1700,2700
P3.0: JP7.36 U2.89 | length 2878.4
  Top Layer w10: U2.89@372.01,1649.53 698.41,1649.53 835.64,1512.29 917.71,1512.29 940,1490 v1(940,1398) ; v1(1123,168) 1445,168 1488,211 v1(1695.3,211)
  Bottom Layer w10: v1(940,1398) 940,1370 980,1330 1046.75,1330 1121,1255.75 1121,1150 1073,1102 1073,1042.5 1091,1024.5 1091,914 1093,912 1093,827.5 1132,788.5 1132,749 1112,729 1112,648 1054,590 1054,540 1074,520 1074,217 v1(1123,168) ; v1(1695.3,211) 1700,206.3 JP7.36@1700,100
P3.22: JP7.35 U2.41 | length 5533.2
  Top Layer w10: U2.41@1075.75,2057.99 1075.75,2167 1126.75,2218 1256,2218 1279,2195 1417,2195 1507,2105 1694.7,2105 1727.7,2138 1848,2138 1916,2070 1916,1930 1927,1919 2583,1919 2740,1762 3032,1762 3084,1710 3084,302.8 3033.2,252 2390,252 2369,231 2369,20 2353,4 1993,4 1951,46 1746,46 JP7.35@1700,0
P3.23: JP7.38 U2.40 | length 3026.6
  Top Layer w10: U2.40@1095.43,2057.99 1095.43,2151.03 1128.4,2184 1248,2184 1255,2177 1399,2177 1489,2087 v1(1789,2087)
  Bottom Layer w10: v1(1789,2087) 1789,2029.95 1984,1834.95 1984,1292 1955,1263 1955,303 1960,298 1960,195 1911,146 1846,146 JP7.38@1800,100
RST: D1.1 JP4.3 JP9.15 S1.1 U2.135 U4.1 U6.12 | length 8569.3
  Top Layer w10: S1.1@-975,2425 S1.1@-725,2425 -725,2670 -670,2725 D1.1@-550,2725 -550,2750 U4.1@-400,2750 ; JP9.15@-900,1650 -865,1685 -687,1685 -687,1607 -691,1603 -691,1512 -683.84,1504.84 -683.84,1432 -631.95,1432 -431.95,1232 v1(-312,1232) ; v1(-196.29,-17.71) -127,-87 610,-87 646,-51 646,21.5 670,45.5 830.5,45.5 846,30 846,-31 890,-75 v1(1185,-75) ; U2.135@977.32,1182.01 977.32,980.68 v1(996,962)
  Bottom Layer w10: S1.1@-975,2425 -849,2299 -849,1701 JP9.15@-900,1650 ; v1(-312,1232) -290.16,1210.16 U6.12@-290.16,1172.05 -290.16,881.59 -251.26,842.68 -251.26,743.74 -286,709 -286,543.71 -233,490.71 -233,378.27 -196.29,341.56 v1(-196.29,-17.71) ; v1(996,962) 991,957 991,511 1054,448 1054,55 1063.5,45.5 1130,45.5 1145.5,30 1145.5,-35.5 ; v1(1185,-75) 1145.5,-35.5 ; JP4.3@2250,300 2298,252 2298,-55 2241,-112 1179,-112 1145.5,-78.5 1145.5,-35.5
RTCK: JP6.36 JP8.2 JP9.11 U2.52 | length 13211.8
  Top Layer w10: v1(-985,2098) -787,2098 v1(-745,2140) ; v1(-900,270) JP8.2@-900,350 ; JP9.11@-900,1450 -807,1543 v1(-753,1543) ; v1(778,-97) 789,-108 2500,-108 v1(2746,138) ; U2.52@859.21,2057.99 859.21,2133.79 858,2135 858,2230 899,2271 1260,2271 1300,2231 1468,2231 1505.49,2193.51 v1(1573,2193.51) ; JP6.36@1700,2800 1753,2853 v1(2728,2853)
  Bottom Layer w10: v1(-985,2098) -985,2030 -1056,1959 -1056,506 JP8.2@-900,350 ; v1(-900,270) -798,168 -798,-59 -750,-107 768,-107 v1(778,-97) ; v1(-753,1543) -753,1917 -656,2014 -656,2110 -686,2140 v1(-745,2140) ; v1(1573,2193.51) 1710.94,2331.45 1710.94,2375 1736,2400.06 1736,2503 1846,2613 1846,2730 1830,2746 1764,2746 1739,2771 1739,2800 JP6.36@1700,2800 ; v1(2728,2853) 2970,2611 3083,2611 3104,2590 3104,190 3052,138 v1(2746,138)
TCK: JP9.9 R9.1 U2.126 | length 2385.7
  Top Layer w10: JP9.9@-900,1350 -780,1470 R9.1@-730,1470 -730,1441 -702,1413 -643,1413 -444,1214 -365,1214 -294,1143 36,1143 98,1205 349,1205 v1(373,1229) ; v1(581,1385) 646,1450 842,1450 852,1440 852,1376.89 800.16,1325.05 U2.126@800.16,1182.01
  Bottom Layer w10: v1(373,1229) 373,1259 398.45,1284.45 398.45,1290 426,1317.55 513.55,1317.55 v1(581,1385)
TDI: JP9.5 R8.2 U2.140 | length 2656.9
  Top Layer w10: JP9.5@-900,1150 -870,1120 R8.2@-730,1120 -730,1080 -683,1033 -683,870 -672,859 -321.12,859 -316.17,854.05 -28.7,854.05 -13.48,869.28 230,869.28 244,855.28 244,765.18 270,739.18 416.18,739.18 488,811 765,811 774,820 774,850 800,876 893.25,876 945.25,928 1036.22,928 1073,964.78 1073,1108.5 1075.75,1111.25 U2.140@1075.75,1182.01
TDO: JP9.13 R12.2 U2.144 | length 6514.6
  Top Layer w10: JP9.13@-900,1550 -805,1645 R12.2@-730,1645 ; v1(-642,2313) -642,2610 -616,2636 -557,2636 -480,2713 -362,2713 -362,2732 -191,2903 1841,2903 v1(1849,2895) ; U2.144@1154.49,1182.01 1154.49,1155 1516,1155 v1(1602,1241)
  Bottom Layer w10: JP9.13@-900,1550 -831,1619 -831,2138 -790,2179 -690,2179 -642,2227 v1(-642,2313) ; v1(1602,1241) 1602,1430 1517,1515 1517,1599 1535,1617 1535,1759 1614,1838 1614,2205 1736,2327 1736,2366 1754,2384 1754,2453 1946,2645 1946,2730 1930,2746 1869,2746 1849,2766 v1(1849,2895)
TMS: JP9.7 R10.2 U2.113 | length 1844
  Top Layer w10: JP9.7@-900,1250 -845,1305 -800,1305 -781,1286 -781,1284 ; R10.2@-730,1295 -770,1295 -781,1284 ; U2.113@544.25,1182.01 544.25,1134 430,1134 395,1169 347,1169 253,1075 -40,1075 -150.95,964.05 -190,964.05 -401.95,1176 -727,1176 -781,1230 -781,1284
TRST: JP9.3 R6.2 U2.43 | length 4920.6
  Top Layer w10: v1(-1018,2051) v1(-786,2051) ; JP9.3@-900,1050 -795,945 R6.2@-730,945 ; v1(1012,2220) 1036.38,2183.77 U2.43@1036.38,2057.99
  Bottom Layer w10: v1(-1018,2051) -1038,2071 -1038,2564 -990,2612 -769,2612 -481,2900 785,2900 850,2835 850,2588.8 886,2552.8 886,2407 1012,2281 v1(1012,2220) ; JP9.3@-900,1050 -848,1102 -848,1575 -808,1615 -808,2029 v1(-786,2051)
pads on no net: JP2.1 JP3.1 JP4.1 JP5.1 JP7.1 JP7.2 JP7.3 JP7.4 JP7.5 JP7.39 JP8.1 U2.5 U2.22 U3.28 U5.28 U6.13 U6.15 Zl1.1 Zl1.6 Zl1.8 Zl1.9

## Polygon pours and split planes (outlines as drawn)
GND on Top Layer (hatched 90Degree grid 10 track 12, remove dead copper): -1100,2950 3200,2950 3200,-150 -1100,-150
GND on Bottom Layer (hatched 90Degree grid 10 track 12, remove dead copper): -1100,2950 3200,2950 3200,-150 -1100,-150

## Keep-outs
Keep-Out Layer:
  lines w10: -1100,-150 3175,-150 3175,2950 -1100,2950 -1100,-150

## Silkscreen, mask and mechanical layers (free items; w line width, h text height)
Top Overlay:
  lines w10: -600,-50 -600,-100 -400,-100 ; -400,-75 -400,-100 ; -325,50 -325,-75 -350,-100 -400,-100 ; 2250,50 2300,0 2525,0 ; 2450,0 2450,50 ; 2525,-75 2525,75
  text "RES" at -900,2550 h60
  text "+3,3V" at 3125,2500 h50 r90
  text "0V" at 3125,2375 h50 r90
  text "+1,8V" at 3125,2100 h50 r90
  text "Rx" at 3125,550 h50 r90
  text "Tx" at 3125,425 h50 r90
  text "On" at 2125,325 h50 r270
  text "1" at -525,300 h50 r270
  text "GND" at 3125,250 h50 r90
  text "On" at -1000,225 h50
  text "Off" at -875,225 h50
  text "Off" at 2125,175 h50 r270
  text "0" at -525,150 h50 r270
  text "BOOT" at -300,150 h60 r270
  text "JTAG" at -1000,125 h60
  text "ISP" at 2550,75 h60 r270
  text "1" at -625,0 h60 r270
  text "0" at -425,0 h60 r270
